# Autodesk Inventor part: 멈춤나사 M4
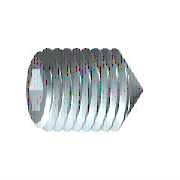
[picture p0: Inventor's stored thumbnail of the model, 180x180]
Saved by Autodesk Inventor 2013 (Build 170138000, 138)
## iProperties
Created: 2012-02
Part Number: 멈춤나사 M4
Material: 강철, 연강
Document SubType Name: Modeling
Standard: JIS B 1177 원추점
Designer: mdu-01
Standards Organization: JIS
Language: ko-KR
Size Designation: M4 x 10
Categories: <MemberInstance><Categories><Category DisplayName="조임쇠" InternalName="e4da775c-781d-43d5-af7c-5136215cf5a6" Mnemonic="FSTN"><Category DisplayName="볼트" InternalN
Density: 1 g/cm^3
IsCustomPart: 1
Author: mdu-01
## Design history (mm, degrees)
sketch "스케치1"
  geometry: L1 (0, 0)-(6.833, 0); L2 (10, 1.155)-(10, 2); L3 (10, 2)-(0, 2); L4 (10, 1.155)-(7.5, 1.155); L5 (7.5, 1.155)-(6.833, 0); L6 (0, -0.4)-(0, 2.4) reference; L7 (0, 2)-(0, 0)
  constraints: 13 end point, 3 parallel, 1 collinear, 1 perpendicular, 1 point on line
  dimensions: "d0" = 2.5 distance of L2.start L4.end (= INTI); "d1" = 60 deg angle of L5 L1; "d2" = 4 diameter of L3 L1 (= NND); "d3" = 2.3094 diameter of L4 L1 (= 1.1547 x SW); "d5" = 10 distance from line of L2 L3.end (= NLG)
revolve "본체" sketch "스케치1" stored, may be unused: angle "d6" = 90 deg
sketch "스케치2"
  geometry: L1 (-0.577, 1)-(0.577, 1); L2 (0.577, 1)-(1.155, 0); L3 (1.155, 0)-(0.577, -1); L4 (0.577, -1)-(-0.577, -1); L5 (-0.577, -1)-(-1.155, 0); L6 (-1.155, 0)-(-0.577, 1); 3 further points
  constraints: 12 end point, 1 coincident, 1 horizontal, 13 other
extrude "슬롯" join sketch "스케치2" taper "d7" = 0 deg; stored distance "d21" = 10
workaxis "Work Axis1"
workplane "Work Plane1"
body "Solid1"
feature "스레드" dims "d12" = 10 (= NLG), "d13" = 0
chamfer "모따기1" distance "d8" = 1.03923 (computed from NND, SPD, FAWI); stored, may be unused: angle "d9" = 60 deg (= FAWI), second distance "d34" = 1.03923 (computed from NND, SPD, FAWI)
chamfer "모따기2" distance "d10" = 0.42941 (= -0.5 x GD1 + 0.5 x NND); stored, may be unused: angle "d11" = 60 deg (= FAWI), second distance "d35" = 0.42941 (= -0.5 x GD1 + 0.5 x NND)
other parameters: "NND" = 4 [user parameter; used in 5 equation terms], "NLG" = 10 [user parameter; used in 2 equation terms], "INTI" = 2.5 [user parameter; used in 1 equation term], "FAWI" = 60 deg [user parameter; used in 4 equation terms], "SW" = 2 [user parameter; used in 2 equation terms], "GD1" = 3.14117 (= THREADDIA - 1.2269 x PTC) [user parameter; used in 2 equation terms], "d4" = 0, "FAWI1" = 45 deg [user parameter], "SPD" = 0.4 [user parameter; used in 2 equation terms], "d36" = 0, "d37" = 0, "GUL" = 0.42941 (= 0.61345 x PTC) [user parameter], "TPU" = 14.28571 (computed from PTC) [user parameter], "TOA" = 30 deg [user parameter], "THREADDIA" = 4 [user parameter; used in 1 equation term], "PTC" = 0.7 [user parameter; used in 4 equation terms], "GAL" = 0.42941 (= 0.61345 x PTC) [user parameter], "E0" = 2.31 (= 1.155 x SW) [user parameter]
